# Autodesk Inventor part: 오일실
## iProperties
IsCustomPart: 0
Company: 한국ATC센터
Created: 2014-10
Part Number: 오일실
Material: 고무
Description: 오일-실
Document SubType Name: Modeling
Standard: KS B 2804
Designer: KYOUNG IL JANG
Standards Organization: KS
Language: ko-KR
Size Designation: D - 17 32 8
Categories: <MemberInstance><Categories><Category DisplayName="샤프트 부품" InternalName="7f7aeb1f-a693-4053-b835-cee3144e0d98" Mnemonic="SHFT"><Category DisplayName="실링" Intern
Density: 0.93 g/cm^3
Mass: 2.28027 g
Surface Area: 32.1224 cm^2
Volume: 2.45191 cm^3
Author: KYOUNG IL JANG
Revision Number: 1
